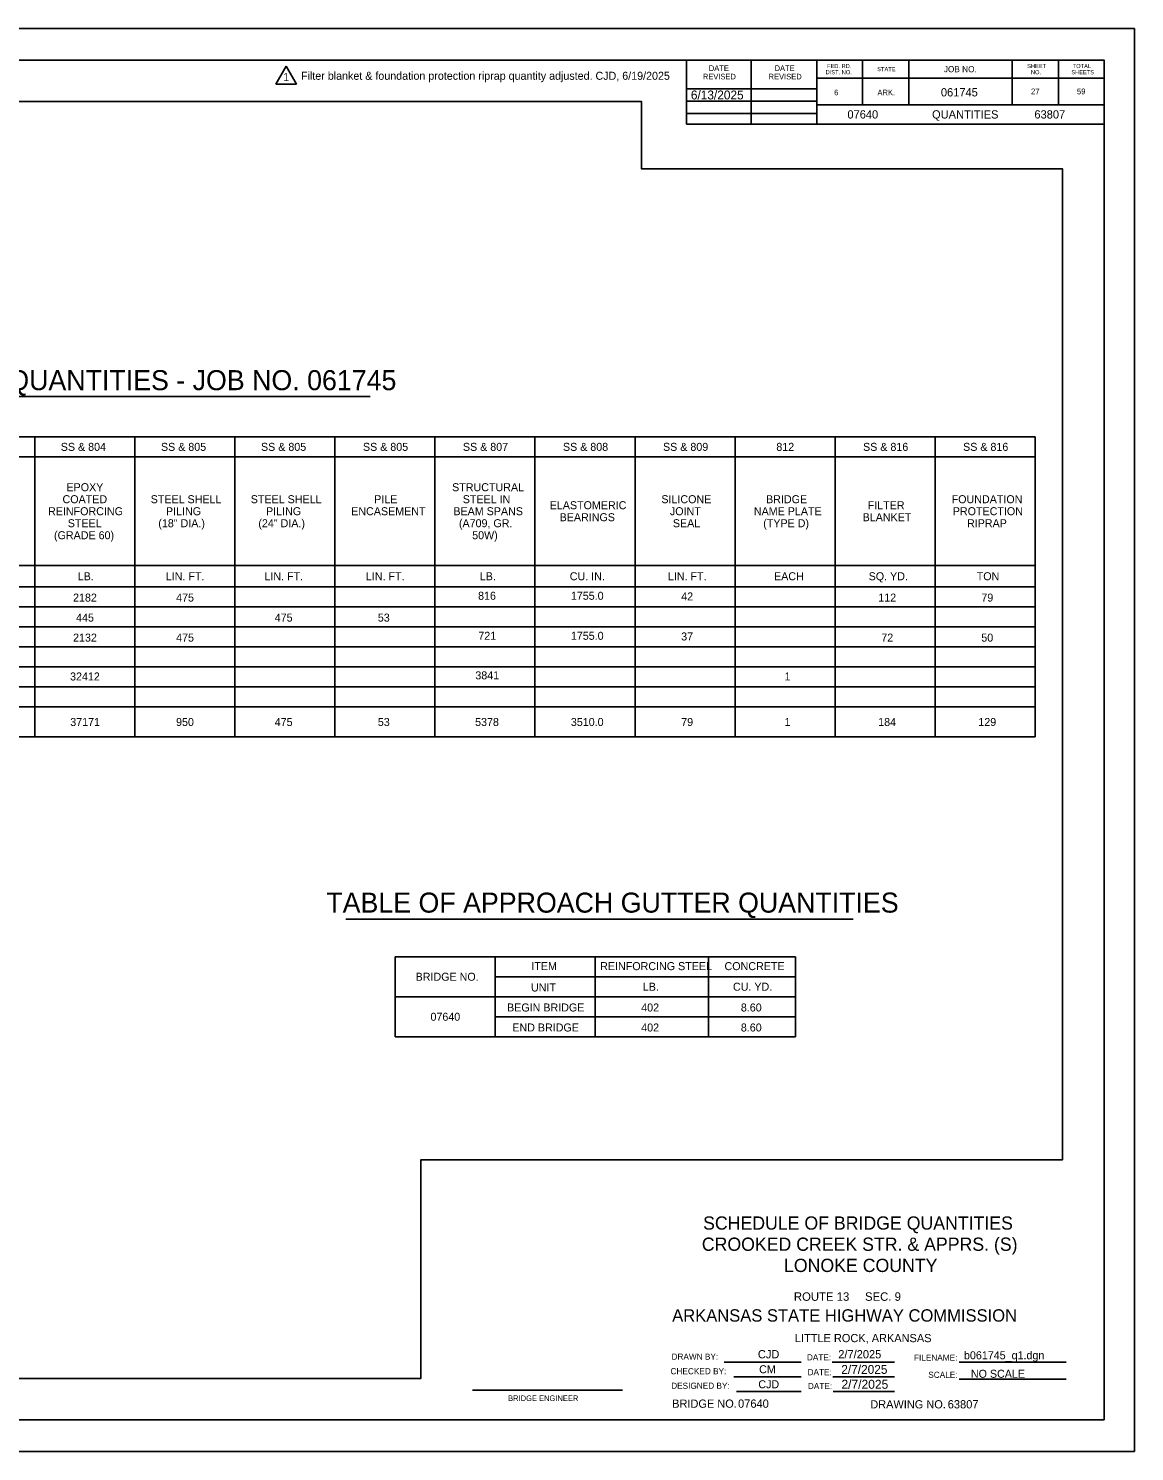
# Model space of a CAD drawing. Extents: x 1390434.7 to 1390467.9, y 1966884.5 to 1966897.9.
# Drawn here: x 1390462.39 to 1390467.92, y 1966889.53 to 1966896.64 of the extents above; entities that cross this region are included whole.
import ezdxf

# ---------------------------------------------------------------- set-up
doc = ezdxf.new("R2010")
doc.units = 0
for name, color, linetype in [('B_Border', 7, 'Continuous'), ('B_No_Plot', 7, 'Continuous'), ('B_Reference_Clip', 7, 'Continuous'), ('Default', 7, 'Continuous')]:
    doc.layers.add(name, color=color, linetype=linetype)

msp = doc.modelspace()

# ---------------------------------------------------------------- linework, layer by layer
at = {"layer": 'B_Border'}
for p, q in [((1390465.6786, 1966896.1644), (1390465.6786, 1966896.4846)), ((1390466.0013, 1966896.1644), (1390466.0013, 1966896.4846)), ((1390466.33, 1966896.1644), (1390466.33, 1966896.4846)), ((1390466.558, 1966896.2617), (1390466.558, 1966896.4846)), ((1390466.7893, 1966896.2617), (1390466.7893, 1966896.4846)), ((1390467.3063, 1966896.4846), (1390467.3063, 1966896.2617)), ((1390467.5376, 1966896.4846), (1390467.5376, 1966896.2617)), ((1390467.7656, 1966896.394), (1390466.33, 1966896.394)), ((1390466.33, 1966896.3407), (1390465.6786, 1966896.3407)), ((1390466.33, 1966896.2795), (1390465.6786, 1966896.2795)), ((1390467.7656, 1966896.2617), (1390466.33, 1966896.2617)), ((1390466.33, 1966896.2184), (1390465.6786, 1966896.2184)), ((1390467.7656, 1966896.1644), (1390465.6786, 1966896.1644)), ((1390465.8666, 1966889.978), (1390466.2523, 1966889.978)), ((1390466.4061, 1966889.978), (1390466.719, 1966889.978)), ((1390467.0413, 1966889.978), (1390467.5756, 1966889.978)), ((1390464.609, 1966889.8374), (1390465.359, 1966889.8374)), ((1390465.9162, 1966889.9035), (1390466.2523, 1966889.9035)), ((1390466.4094, 1966889.9035), (1390466.719, 1966889.9035)), ((1390467.0423, 1966889.892), (1390467.5756, 1966889.892)), ((1390465.9284, 1966889.8308), (1390466.2523, 1966889.8308)), ((1390466.4111, 1966889.8308), (1390466.719, 1966889.8308))]:
    msp.add_line(p, q, dxfattribs=at)
msp.add_lwpolyline([(1390467.7656, 1966889.6885), (1390457.2273, 1966889.6885), (1390457.2273, 1966896.4846), (1390467.7656, 1966896.4846)], close=True, dxfattribs=at)
at = {"layer": 'B_No_Plot'}
for p, q in [((1390456.7514, 1966896.6426), (1390467.9181, 1966896.6426)), ((1390467.9181, 1966896.6426), (1390467.9181, 1966889.5306)), ((1390467.9181, 1966889.5306), (1390456.7514, 1966889.5306))]:
    msp.add_line(p, q, dxfattribs=at)
at = {"layer": 'B_Reference_Clip'}
msp.add_lwpolyline([(1390457.4356, 1966896.2779), (1390465.4538, 1966896.2779), (1390465.4538, 1966895.9413), (1390467.5573, 1966895.9413), (1390467.5573, 1966890.988), (1390464.351, 1966890.988), (1390464.351, 1966889.8953), (1390457.4356, 1966889.8953)], close=True, dxfattribs=at)
at = {"layer": 'Default'}
for p, q in [((1390463.6256, 1966896.3647), (1390463.6776, 1966896.4548)), ((1390463.6776, 1966896.4548), (1390463.7296, 1966896.3647)), ((1390463.7296, 1966896.3647), (1390463.6256, 1966896.3647)), ((1390460.7512, 1966894.8025), (1390464.0972, 1966894.8025)), ((1390461.9216, 1966894.6016), (1390462.4216, 1966894.6016)), ((1390462.4216, 1966894.6016), (1390462.4216, 1966893.1016)), ((1390462.4216, 1966894.6016), (1390462.9216, 1966894.6016)), ((1390462.9216, 1966894.6016), (1390462.9216, 1966893.1016)), ((1390462.9216, 1966894.6016), (1390463.4216, 1966894.6016)), ((1390463.4216, 1966894.6016), (1390463.4216, 1966893.1016)), ((1390463.4216, 1966894.6016), (1390463.9216, 1966894.6016)), ((1390463.9216, 1966894.6016), (1390463.9216, 1966893.1016)), ((1390463.9216, 1966894.6016), (1390464.4216, 1966894.6016)), ((1390464.4216, 1966894.6016), (1390464.4216, 1966893.1016)), ((1390464.4216, 1966894.6016), (1390464.9216, 1966894.6016)), ((1390464.9216, 1966894.6016), (1390464.9216, 1966893.1016)), ((1390464.9216, 1966894.6016), (1390465.4216, 1966894.6016)), ((1390465.4216, 1966894.6016), (1390465.4216, 1966893.1016)), ((1390465.4216, 1966894.6016), (1390465.9216, 1966894.6016)), ((1390465.9216, 1966894.6016), (1390465.9216, 1966893.1016)), ((1390465.9216, 1966894.6016), (1390466.4216, 1966894.6016)), ((1390466.4216, 1966894.6016), (1390466.4216, 1966893.1016)), ((1390466.4216, 1966894.6016), (1390466.9216, 1966894.6016)), ((1390466.9216, 1966894.6016), (1390466.9216, 1966893.1016)), ((1390466.9216, 1966894.6016), (1390467.4216, 1966894.6016)), ((1390467.4216, 1966894.6016), (1390467.4216, 1966893.1016)), ((1390458.9216, 1966894.5016), (1390467.4216, 1966894.5016)), ((1390461.9216, 1966893.9582), (1390462.4216, 1966893.9582)), ((1390462.4216, 1966893.9582), (1390462.9216, 1966893.9582)), ((1390462.9216, 1966893.9582), (1390463.9216, 1966893.9582)), ((1390463.9216, 1966893.9582), (1390464.4216, 1966893.9582)), ((1390464.4216, 1966893.9582), (1390464.9216, 1966893.9582)), ((1390464.9216, 1966893.9582), (1390465.4216, 1966893.9582)), ((1390465.4216, 1966893.9582), (1390465.9216, 1966893.9582)), ((1390465.9216, 1966893.9582), (1390466.4216, 1966893.9582)), ((1390466.4216, 1966893.9582), (1390466.9216, 1966893.9582)), ((1390466.9216, 1966893.9582), (1390467.4216, 1966893.9582)), ((1390461.9216, 1966893.8516), (1390462.4216, 1966893.8516)), ((1390462.4216, 1966893.8516), (1390462.9216, 1966893.8516)), ((1390462.9216, 1966893.8516), (1390463.9216, 1966893.8516)), ((1390463.9216, 1966893.8516), (1390464.4216, 1966893.8516)), ((1390464.4216, 1966893.8516), (1390464.9216, 1966893.8516)), ((1390464.9216, 1966893.8516), (1390465.4216, 1966893.8516)), ((1390465.4216, 1966893.8516), (1390465.9216, 1966893.8516)), ((1390465.9216, 1966893.8516), (1390466.4216, 1966893.8516)), ((1390466.4216, 1966893.8516), (1390466.9216, 1966893.8516)), ((1390466.9216, 1966893.8516), (1390467.4216, 1966893.8516)), ((1390457.9216, 1966893.7516), (1390466.9216, 1966893.7516)), ((1390458.4216, 1966893.7516), (1390467.4216, 1966893.7516)), ((1390457.9216, 1966893.6516), (1390467.4216, 1966893.6516)), ((1390457.9216, 1966893.5516), (1390467.4216, 1966893.5516)), ((1390457.9216, 1966893.4516), (1390467.4216, 1966893.4516)), ((1390457.9216, 1966893.3516), (1390467.4216, 1966893.3516)), ((1390457.9216, 1966893.2516), (1390467.4216, 1966893.2516)), ((1390457.9216, 1966893.1016), (1390467.4216, 1966893.1016)), ((1390463.9769, 1966892.1915), (1390466.5122, 1966892.1915)), ((1390464.2231, 1966892.0034), (1390464.7231, 1966892.0034)), ((1390464.2231, 1966892.0034), (1390464.2231, 1966891.6034)), ((1390464.7231, 1966892.0034), (1390465.2231, 1966892.0034)), ((1390464.7231, 1966892.0034), (1390464.7231, 1966891.6034)), ((1390465.2231, 1966892.0034), (1390465.7231, 1966892.0034)), ((1390465.2231, 1966892.0034), (1390465.2231, 1966891.6034)), ((1390465.7231, 1966892.0034), (1390466.2231, 1966892.0034)), ((1390465.7892, 1966892.0034), (1390465.7892, 1966891.6034)), ((1390466.2231, 1966892.0034), (1390466.2231, 1966891.6034)), ((1390464.7231, 1966891.9034), (1390466.2231, 1966891.9034)), ((1390464.2231, 1966891.8034), (1390466.2231, 1966891.8034)), ((1390464.7231, 1966891.7034), (1390466.2231, 1966891.7034)), ((1390464.2231, 1966891.6034), (1390466.2231, 1966891.6034))]:
    msp.add_line(p, q, dxfattribs=at)

# ---------------------------------------------------------------- texts
at = {"layer": 'B_Border'}
for s, height, p in [('DATE', 0.02811, (1390465.7904, 1966896.4301)), ('DATE', 0.02811, (1390466.1191, 1966896.4301)), ('FED. RD.', 0.0205, (1390466.3814, 1966896.4444)), ('STATE', 0.0205, (1390466.6322, 1966896.4291)), ('JOB NO.', 0.03076, (1390466.9651, 1966896.4239)), ('SHEET', 0.0205, (1390467.3812, 1966896.4444)), ('TOTAL', 0.0205, (1390467.6094, 1966896.4444)), ('1', 0.04, (1390463.663, 1966896.3795)), ('REVISED', 0.02811, (1390465.7607, 1966896.3879)), ('REVISED', 0.02811, (1390466.0893, 1966896.3879)), ('DIST. NO.', 0.0205, (1390466.3742, 1966896.4137)), ('NO.', 0.0205, (1390467.4005, 1966896.4137)), ('SHEETS', 0.0205, (1390467.6023, 1966896.4137)), ('6/13/2025', 0.04432, (1390465.7007, 1966896.288)), ('6', 0.0281, (1390466.4167, 1966896.3087)), ('ARK.', 0.02811, (1390466.6333, 1966896.3087)), ('061745', 0.04135, (1390466.9503, 1966896.3029)), ('27', 0.02899, (1390467.4005, 1966896.3133)), ('59', 0.02899, (1390467.63, 1966896.3133)), ('07640', 0.04135, (1390466.4831, 1966896.1924)), ('      QUANTITIES', 0.041349, (1390466.8139, 1966896.1924)), ('       63807', 0.041349, (1390467.3101, 1966896.1924)), ('SS & 807', 0.04, (1390464.5613, 1966894.5316)), ('SILICONE', 0.04, (1390465.5532, 1966894.2699)), ('JOINT ', 0.04, (1390465.5959, 1966894.2099)), ('SEAL', 0.04, (1390465.6107, 1966894.1499)), ('TON', 0.04, (1390467.1294, 1966893.8849)), ('2182', 0.04, (1390462.6128, 1966893.7783)), ('816', 0.04, (1390464.6371, 1966893.7874)), ('1755.0', 0.04, (1390465.1009, 1966893.7874)), ('42', 0.04, (1390465.6524, 1966893.7841)), ('112', 0.04, (1390466.6374, 1966893.7783)), ('79', 0.04, (1390467.1524, 1966893.7783)), ('445', 0.04, (1390462.628, 1966893.6783)), ('53', 0.04, (1390464.1361, 1966893.6783)), ('2132', 0.04, (1390462.6128, 1966893.5783)), ('721', 0.04, (1390464.6384, 1966893.5874)), ('1755.0', 0.04, (1390465.1009, 1966893.5874)), ('37', 0.04, (1390465.6522, 1966893.5841)), ('72', 0.04, (1390466.6524, 1966893.5783)), ('50', 0.04, (1390467.1523, 1966893.5783)), ('32412', 0.04, (1390462.5978, 1966893.3841)), ('37171', 0.04, (1390462.5988, 1966893.1566)), ('5378', 0.04, (1390464.6222, 1966893.1566)), ('3510.0', 0.04, (1390465.1009, 1966893.1566)), ('184', 0.04, (1390466.6369, 1966893.1566)), ('129', 0.04, (1390467.1374, 1966893.1566)), ('402', 0.04, (1390465.4524, 1966891.7298)), ('8.60', 0.04, (1390465.9505, 1966891.7298)), ('8.60', 0.04, (1390465.9505, 1966891.6298)), ('SCHEDULE OF BRIDGE QUANTITIES', 0.066158, (1390465.7618, 1966890.6395)), ('CROOKED CREEK STR. & APPRS. (S)', 0.066158, (1390465.7554, 1966890.5337)), ('LONOKE COUNTY', 0.066158, (1390466.1662, 1966890.4278)), ('ROUTE 13     SEC. 9', 0.042335, (1390466.2156, 1966890.2839)), ('ARKANSAS STATE HIGHWAY COMMISSION', 0.061855, (1390465.6073, 1966890.1797)), ('LITTLE ROCK, ARKANSAS', 0.041015, (1390466.2206, 1966890.0772)), ('DRAWN BY:', 0.03076, (1390465.604, 1966889.9895)), ('CJD', 0.04135, (1390466.0355, 1966889.9962)), ('DATE:', 0.03076, (1390466.2806, 1966889.9862)), ('2/7/2025', 0.04135, (1390466.4373, 1966889.9962)), ('FILENAME:', 0.03076, (1390466.8156, 1966889.9846)), ('b061745_q1.dgn', 0.04, (1390467.0657, 1966889.9917)), ('CHECKED BY:', 0.030764, (1390465.599, 1966889.9168)), ('CM', 0.04, (1390466.0419, 1966889.9218)), ('DATE:', 0.03076, (1390466.284, 1966889.9118)), ('2/7/2025', 0.04432, (1390466.4525, 1966889.9188)), ('SCALE:', 0.03076, (1390466.8873, 1966889.8986)), ('NO SCALE', 0.04, (1390467.1002, 1966889.8992)), ('DESIGNED BY:', 0.030764, (1390465.6023, 1966889.844)), ('CJD', 0.04, (1390466.0379, 1966889.8467)), ('DATE:', 0.03076, (1390466.2856, 1966889.8423)), ('2/7/2025', 0.04498, (1390466.4532, 1966889.8442)), ('BRIDGE ENGINEER', 0.028114, (1390464.7873, 1966889.7828)), ('BRIDGE NO. ', 0.041015, (1390465.6073, 1966889.7494)), ('07640', 0.04135, (1390465.9365, 1966889.7494)), ('DRAWING NO. ', 0.041015, (1390466.5973, 1966889.7461)), ('63807', 0.04135, (1390466.9844, 1966889.7461))]:
    msp.add_text(s, height=height, dxfattribs=at).set_placement(p)
for s, height, p in [('SCHEDULE OF BRIDGE QUANTITIES - JOB NO. 061745', 0.1, (1390460.7512, 1966894.8349)), ('SS & 804', 0.04, (1390462.5514, 1966894.5316)), ('SS & 805', 0.04, (1390463.0521, 1966894.5316)), ('SS & 805', 0.04, (1390463.5521, 1966894.5316)), ('SS & 805', 0.04, (1390464.0617, 1966894.5316)), ('SS & 808', 0.04, (1390465.0613, 1966894.5316)), ('SS & 809', 0.04, (1390465.5614, 1966894.5316)), ('812', 0.04, (1390466.1278, 1966894.5316)), ('SS & 816', 0.04, (1390466.5612, 1966894.5316)), ('SS & 816', 0.04, (1390467.0612, 1966894.5316)), ('EPOXY', 0.04, (1390462.5799, 1966894.3299)), ('STRUCTURAL', 0.04, (1390464.5073, 1966894.3299)), ('REINFORCING', 0.04, (1390462.4878, 1966894.2099)), ('COATED', 0.04, (1390462.5602, 1966894.2699)), ('STEEL SHELL', 0.04, (1390463.0008, 1966894.2699)), ('PILING', 0.04, (1390463.0772, 1966894.2099)), ('STEEL SHELL', 0.04, (1390463.5009, 1966894.2699)), ('PILING', 0.04, (1390463.5773, 1966894.2099)), ('ENCASEMENT', 0.04, (1390464.003, 1966894.2099)), ('PILE', 0.04, (1390464.118, 1966894.2699)), ('BEAM SPANS', 0.04, (1390464.5136, 1966894.2099)), ('STEEL IN', 0.04, (1390464.5604, 1966894.2699)), ('ELASTOMERIC', 0.04, (1390464.9951, 1966894.2399)), ('NAME PLATE', 0.04, (1390466.0155, 1966894.2099)), ('BRIDGE', 0.04, (1390466.0765, 1966894.2699)), ('FILTER', 0.04, (1390466.5843, 1966894.2399)), ('FOUNDATION ', 0.04, (1390467.0041, 1966894.2699)), ('PROTECTION', 0.04, (1390467.0097, 1966894.2099)), ('STEEL', 0.04, (1390462.5861, 1966894.1499)), ('(18" DIA.)', 0.04, (1390463.0389, 1966894.1499)), ('(24" DIA.)', 0.04, (1390463.539, 1966894.1499)), ('(A709, GR.', 0.04, (1390464.5414, 1966894.1499)), ('BEARINGS', 0.04, (1390465.0447, 1966894.1799)), ('(TYPE D)', 0.04, (1390466.0622, 1966894.1499)), ('BLANKET', 0.04, (1390466.5591, 1966894.1799)), ('RIPRAP', 0.04, (1390467.0808, 1966894.1499)), ('(GRADE 60)', 0.04, (1390462.5177, 1966894.0899)), ('50W)', 0.04, (1390464.6076, 1966894.0899)), ('LB.', 0.04, (1390462.636, 1966893.8849)), ('LIN. FT.', 0.04, (1390463.0763, 1966893.8849)), ('LIN. FT.', 0.04, (1390463.5692, 1966893.8849)), ('LIN. FT.', 0.04, (1390464.0763, 1966893.8849)), ('LB.', 0.04, (1390464.6456, 1966893.8849)), ('CU. IN.', 0.04, (1390465.0954, 1966893.8849)), ('LIN. FT.', 0.04, (1390465.5859, 1966893.8849)), ('EACH', 0.04, (1390466.1163, 1966893.8849)), ('SQ. YD.', 0.04, (1390466.5893, 1966893.8849)), ('475', 0.04, (1390463.128, 1966893.7783)), ('475', 0.04, (1390463.6209, 1966893.6783)), ('475', 0.04, (1390463.128, 1966893.5783)), ('3841', 0.04, (1390464.6234, 1966893.3896)), ('1', 0.04, (1390466.1685, 1966893.3841)), ('950', 0.04, (1390463.1277, 1966893.1566)), ('475', 0.04, (1390463.6209, 1966893.1566)), ('53', 0.04, (1390464.1361, 1966893.1566)), ('79', 0.04, (1390465.6524, 1966893.1566)), ('1', 0.04, (1390466.1685, 1966893.1566)), ('TABLE OF APPROACH GUTTER QUANTITIES ', 0.1, (1390463.8786, 1966892.2239)), ('ITEM', 0.04, (1390464.9034, 1966891.9364)), ('REINFORCING STEEL', 0.04, (1390465.2474, 1966891.9364)), ('CONCRETE', 0.04, (1390465.8688, 1966891.9364)), ('BRIDGE NO.', 0.04, (1390464.325, 1966891.8834)), ('UNIT', 0.04, (1390464.9016, 1966891.8298)), ('LB.', 0.04, (1390465.4606, 1966891.8336)), ('CU. YD.', 0.04, (1390465.911, 1966891.8336)), ('BEGIN BRIDGE', 0.04, (1390464.782, 1966891.7298)), ('07640', 0.04, (1390464.3992, 1966891.6834)), ('END BRIDGE', 0.04, (1390464.8082, 1966891.6298)), ('402', 0.04, (1390465.4524, 1966891.6298))]:
    msp.add_text(s, height=height, rotation=360, dxfattribs=at).set_placement(p)
at = {"layer": 'Default'}
msp.add_text('Filter blanket & foundation protection riprap quantity adjusted. CJD, 6/19/2025 ', height=0.04, dxfattribs=at).set_placement((1390463.7522, 1966896.3861))

doc.saveas('drawing.dxf')
